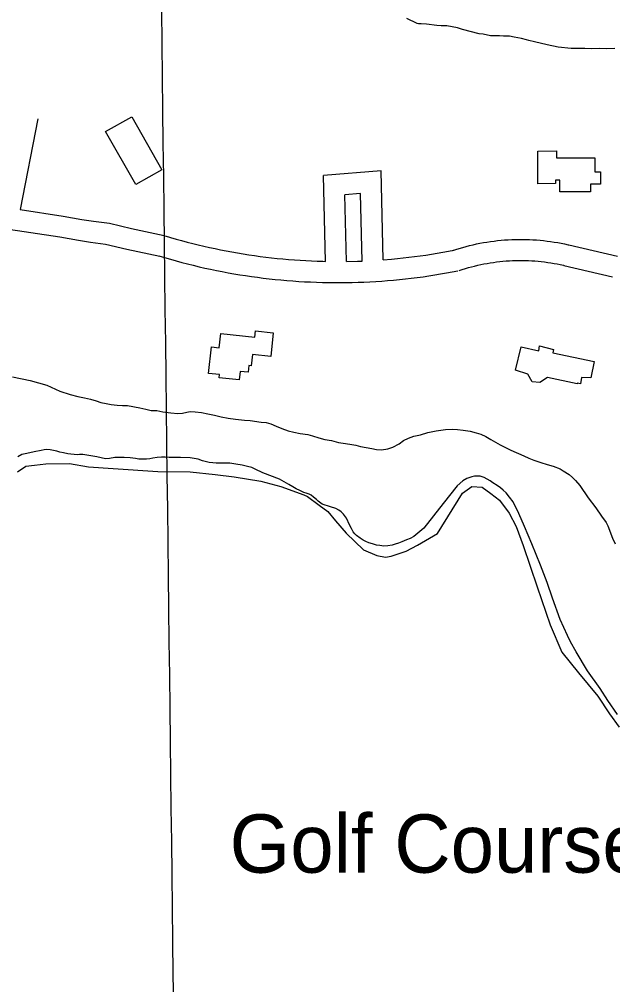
# Model space of a CAD drawing. Extents: x 3704301 to 3742427, y 506229 to 532009.
# Drawn here: x 3718892 to 3719736, y 513417 to 514791 of the extents above; entities that cross this region are included whole.
import ezdxf

# ---------------------------------------------------------------- set-up
doc = ezdxf.new("R2010")
doc.units = 0
for name, color, linetype in [('V-BLDG-IDEN', 7, 'Continuous'), ('V-BLDG-OTLN', 7, 'Continuous'), ('V-GRID-MAJR', 7, 'Continuous'), ('V-ROAD-CNTR', 7, 'Continuous'), ('V-SITE-OTLN', 7, 'Continuous'), ('V-SITE-VEGE', 7, 'Continuous'), ('V-TOPO-SHOR', 7, 'Continuous')]:
    doc.layers.add(name, color=color, linetype=linetype)

msp = doc.modelspace()

# ---------------------------------------------------------------- linework, layer by layer
at = {"layer": 'V-BLDG-OTLN'}
for points in [[(3719051.562, 514652.261), (3719094.589, 514576.799), (3719057.545, 514555.678), (3719014.518, 514631.14)], [(3719629.7660000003, 514557.06200000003), (3719629.682, 514603.57), (3719655.978, 514603.619), (3719655.997, 514593.963), (3719710.793, 514594.063), (3719710.83, 514573.936), (3719718.551, 514573.95), (3719718.5840000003, 514556.478), (3719704.631, 514556.456), (3719704.651, 514545.483), (3719660.861, 514545.401), (3719660.828, 514562.264), (3719654.617, 514562.254), (3719654.6210000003, 514557.10500000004)], [(3719252.873, 514344.902), (3719249.3710000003, 514311.04600000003), (3719223.345, 514313.737), (3719221.698, 514297.83), (3719218.4620000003, 514298.164), (3719217.485, 514288.707), (3719205.9080000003, 514289.905), (3719204.648, 514277.733), (3719176.14, 514280.68200000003), (3719176.617, 514285.297), (3719161.079, 514286.90400000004), (3719164.987, 514324.7), (3719176.191, 514323.543), (3719178.27, 514343.63800000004), (3719226.605, 514338.639), (3719227.531, 514347.523)], [(3719685.341, 514272.21400000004), (3719643.287, 514280.988), (3719632.5840000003, 514274.053), (3719621.748, 514275.229), (3719615.489, 514285.94200000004), (3719597.819, 514291.73600000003), (3719606.063, 514324.993), (3719631.167, 514319.32), (3719631.7320000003, 514326.091), (3719652.095, 514321.016), (3719650.8200000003, 514316.262), (3719709.8370000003, 514303.708), (3719704.807, 514280.64400000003), (3719691.9560000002, 514281.108), (3719690.071, 514272.292), (3719685.554, 514273.232)]]:
    msp.add_lwpolyline(points, close=True, dxfattribs=at)
at = {"layer": 'V-GRID-MAJR'}
msp.add_spline([(3719130.791, 511775.213), (3719057.661, 517832.646), (3718984.494, 523893.163), (3718911.326, 529953.694), (3718911.289, 529956.764)], degree=3, dxfattribs=at)
at = {"layer": 'V-ROAD-CNTR'}
for points in [[(3718917.9881250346, 514649.22467537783), (3718892.7591754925, 514520.16793349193)], [(3719406.4941480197, 514575.5548227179), (3719324.34931231, 514568.9508359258)], [(3719327.3513063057, 514446.467080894), (3719324.34931231, 514568.9508359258)], [(3719409.6041418, 514448.69007644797), (3719406.4941480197, 514575.5548227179)], [(3719377.2812064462, 514543.10888760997), (3719355.037250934, 514541.320891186)], [(3719357.3642462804, 514446.28908124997), (3719355.037250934, 514541.320891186)], [(3719379.636201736, 514446.97207988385), (3719377.2812064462, 514543.10888760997)], [(3718892.758175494, 514520.16793349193), (3718953.9110531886, 514511.00695181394), (3718980.7559994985, 514506.2889612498), (3718997.365966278, 514503.6829664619), (3719019.8249213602, 514500.70997240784), (3719051.2918584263, 514493.30198722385), (3719097.89476522, 514483.1960074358)], [(3718783.6913936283, 514506.1709614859), (3718949.091062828, 514481.3950110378), (3718975.8340093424, 514476.69502043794), (3718993.071974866, 514473.98902584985), (3719014.406932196, 514471.16603149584), (3719044.6758716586, 514464.040045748), (3719091.536777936, 514453.878066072)], [(3719099.0117629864, 514482.90900800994), (3719106.89474722, 514480.5520127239), (3719114.7297315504, 514478.29201724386), (3719122.586715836, 514476.10702161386), (3719130.4637000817, 514473.99802583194), (3719138.360684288, 514471.96602989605), (3719146.2766684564, 514470.00903380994), (3719154.212652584, 514468.13003756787), (3719162.1656366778, 514466.32604117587), (3719170.13462074, 514464.59904462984), (3719178.120604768, 514462.94904793), (3719186.1225887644, 514461.37605107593), (3719194.1395727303, 514459.88105406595), (3719202.1695566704, 514458.46305690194), (3719210.21454058, 514457.1220595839), (3719218.2695244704, 514455.8580621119), (3719226.336508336, 514454.673064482), (3719234.4164921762, 514453.56606669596), (3719242.506475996, 514452.5360687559), (3719250.605459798, 514451.5840706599), (3719258.713443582, 514450.71007240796), (3719266.8294273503, 514449.9140739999), (3719274.951411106, 514449.19707543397), (3719283.080394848, 514448.55907671), (3719291.2173785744, 514447.998077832), (3719299.357362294, 514447.51607879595), (3719307.502346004, 514447.113079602), (3719315.6513297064, 514446.78808025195), (3719323.800313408, 514446.5410807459), (3719327.3513063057, 514446.467080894)], [(3719508.280944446, 514462.007049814), (3719512.9659350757, 514463.5390467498), (3719517.795925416, 514465.031043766), (3719522.64891571, 514466.441040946), (3719527.5259059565, 514467.7720382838), (3719532.4258961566, 514469.0210357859), (3719537.34388632, 514470.1880334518), (3719542.280876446, 514471.2720312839), (3719547.234866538, 514472.27502927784), (3719552.205856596, 514473.19502743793), (3719557.1918466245, 514474.032025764), (3719562.18883663, 514474.786024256), (3719567.200826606, 514475.45602291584), (3719572.2198165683, 514476.0430217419), (3719577.249806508, 514476.5470207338), (3719582.287796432, 514476.96701989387), (3719587.3317863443, 514477.3020192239), (3719592.3797762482, 514477.55401871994), (3719597.431766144, 514477.72201838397), (3719602.487756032, 514477.8050182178), (3719607.540745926, 514477.80401821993), (3719612.594735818, 514477.72001838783), (3719617.64872571, 514477.550018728), (3719622.6967156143, 514477.2970192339), (3719627.739705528, 514476.960019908), (3719632.777695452, 514476.5390207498), (3719637.806685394, 514476.0350217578), (3719642.8276753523, 514475.447022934), (3719647.837665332, 514474.77402427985), (3719652.836655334, 514474.01902579), (3719657.8206453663, 514473.18002746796), (3719662.790635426, 514472.25902931), (3719667.7466255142, 514471.25503131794), (3719672.6286157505, 514470.1810334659), (3719673.556613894, 514469.96703389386)], [(3719409.6041418, 514448.69007644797), (3719421.553117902, 514449.7130744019), (3719429.6691016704, 514450.48707285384), (3719437.780085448, 514451.34007114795), (3719445.881069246, 514452.27106928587), (3719453.97405306, 514453.2800672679), (3719462.0560368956, 514454.36606509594), (3719470.127020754, 514455.53106276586), (3719478.187004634, 514456.773060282), (3719486.2339885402, 514458.093057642), (3719494.267972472, 514459.49005484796), (3719502.2889564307, 514460.96505189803), (3719510.0929408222, 514462.47604887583)], [(3719673.6166137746, 514469.95303392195), (3719742.8794752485, 514453.742066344)], [(3719090.4197801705, 514454.16506549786), (3719098.4407641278, 514451.768070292), (3719106.553747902, 514449.42807497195), (3719114.688731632, 514447.16507949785), (3719122.8457153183, 514444.982083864), (3719131.022698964, 514442.87608807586), (3719139.2206825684, 514440.85109212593), (3719147.4366661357, 514438.90409602), (3719155.671649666, 514437.036099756), (3719163.9246331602, 514435.2491033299), (3719172.192616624, 514433.54110674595), (3719180.478600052, 514431.91211000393), (3719188.7795834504, 514430.363113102), (3719197.0935668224, 514428.89511603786), (3719205.422550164, 514427.5061188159), (3719213.765533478, 514426.19812143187), (3719222.120516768, 514424.9711238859), (3719230.4845000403, 514423.82412617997), (3719238.860483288, 514422.7581283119), (3719247.2474665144, 514421.7721302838), (3719255.6434497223, 514420.868132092), (3719264.0454329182, 514420.04413373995), (3719272.457416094, 514419.30113522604), (3719280.876399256, 514418.63913654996), (3719289.29938241, 514418.060137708), (3719297.72936555, 514417.56013870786), (3719306.1623486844, 514417.14313954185), (3719314.59933181, 514416.8061402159), (3719323.040314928, 514416.55114072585), (3719331.4822980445, 514416.3781410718), (3719339.925281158, 514416.28514125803), (3719348.368264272, 514416.2741412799), (3719356.8122473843, 514416.34414114), (3719365.2552304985, 514416.49614083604), (3719373.6962136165, 514416.7291403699), (3719382.1351967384, 514417.04413974), (3719390.568179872, 514417.440138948), (3719398.9981630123, 514417.91713799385), (3719407.42414616, 514418.475136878), (3719415.8441293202, 514419.11513559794), (3719424.257112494, 514419.8351341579), (3719432.6630956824, 514420.63713255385), (3719441.060078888, 514421.52013078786), (3719449.44906211, 514422.48312886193), (3719457.828045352, 514423.5281267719), (3719466.196028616, 514424.6521245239), (3719474.5550118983, 514425.8591221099), (3719482.8989952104, 514427.14511953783), (3719491.2319785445, 514428.51111680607), (3719499.551961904, 514429.95811391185), (3719507.8549452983, 514431.485110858), (3719515.796929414, 514433.02410778)], [(3719357.3642462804, 514446.28908124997), (3719372.722215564, 514446.7130804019), (3719379.636201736, 514446.97207988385)], [(3719517.60892579, 514433.4931068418), (3719522.057916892, 514434.94910393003), (3719526.409908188, 514436.2931012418), (3719530.784899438, 514437.5650986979), (3719535.179890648, 514438.7640962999), (3719539.5938818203, 514439.8890940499), (3719544.0258729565, 514440.9400919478), (3719548.474864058, 514441.91808999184), (3719552.9408551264, 514442.82108818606), (3719557.4198461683, 514443.65108652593), (3719561.911837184, 514444.40408501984), (3719566.416828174, 514445.0840836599), (3719570.9308191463, 514445.6880824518), (3719575.4578100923, 514446.217081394), (3719579.9898010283, 514446.67108048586), (3719584.5297919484, 514447.0490797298), (3719589.07378286, 514447.35207912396), (3719593.6257737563, 514447.57807867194), (3719598.1777646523, 514447.730078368), (3719602.7317555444, 514447.805078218), (3719607.2887464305, 514447.8040782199), (3719611.8427373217, 514447.728078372), (3719616.394728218, 514447.576078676), (3719620.944719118, 514447.347079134), (3719625.491710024, 514447.04407973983), (3719630.029700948, 514446.665080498), (3719634.5626918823, 514446.20908140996), (3719639.087682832, 514445.67908246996), (3719643.601673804, 514445.07408367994), (3719648.106664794, 514444.393085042), (3719652.5986558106, 514443.6380865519), (3719657.0786468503, 514442.8070882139), (3719661.5426379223, 514441.90309002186), (3719666.044628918, 514440.91109200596), (3719666.840627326, 514440.7290923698)], [(3719666.7806274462, 514440.74309234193), (3719736.04348892, 514424.532124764)]]:
    msp.add_lwpolyline(points, dxfattribs=at)
at = {"layer": 'V-SITE-OTLN'}
for points in [[(3718888.855, 514146.702), (3718900.889, 514155.011), (3718913.034, 514156.563), (3718929.231, 514158.179), (3718963.0270000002, 514158.734), (3718990.151, 514153.768), (3719025.344, 514151.64), (3719088.967, 514147.272), (3719134.951, 514146.674), (3719170.164, 514143.19200000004), (3719197.267, 514139.579), (3719235.227, 514133.439), (3719263.752, 514125.792), (3719296.393, 514114.158), (3719301.842, 514111.542), (3719318.2630000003, 514099.641), (3719330.5840000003, 514090.378), (3719341.6210000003, 514077.038), (3719356.778, 514059.707), (3719381.5100000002, 514035.772), (3719400.568, 514027.972), (3719412.778, 514025.467), (3719420.866, 514026.952), (3719442.384, 514034.064), (3719458.473, 514042.441), (3719486.597, 514059.128), (3719522.166, 514116.5), (3719535.529, 514126.183), (3719550.4220000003, 514125.075), (3719562.7430000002, 514115.81200000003), (3719575.0640000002, 514106.549), (3719588.892, 514087.84500000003), (3719598.663, 514069.075), (3719608.569, 514042.193), (3719628.468, 513983.022), (3719646.926, 513929.237), (3719663.789, 513890.30100000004), (3719687.258, 513860.93700000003), (3719714.844, 513827.585), (3719731.488, 513802.16500000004)], [(3719731.488, 513802.16500000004), (3719745.316, 513783.461)]]:
    msp.add_lwpolyline(points, dxfattribs=at)
at = {"layer": 'V-SITE-VEGE'}
msp.add_lwpolyline([(3719739.1010000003, 514749.369), (3719727.14, 514748.89), (3719717.904, 514749.482), (3719705.401, 514749.005), (3719696.707, 514749.59500000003), (3719677.142, 514749.697), (3719658.6720000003, 514751.425), (3719642.929, 514754.77), (3719625.017, 514759.212), (3719616.872, 514760.887), (3719613.6180000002, 514761.99100000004), (3719606.56, 514763.658), (3719595.702, 514765.891), (3719589.185, 514767.015), (3719580.489, 514767.058), (3719575.058, 514767.629), (3719562.0160000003, 514767.701), (3719551.698, 514769.927), (3719546.267, 514770.501), (3719522.3850000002, 514776.606), (3719515.33, 514778.815), (3719500.128, 514781.613), (3719491.975, 514781.65400000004), (3719486.001, 514782.232), (3719471.335, 514783.94), (3719463.7290000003, 514784.523), (3719459.923, 514784.544), (3719457.753, 514785.099), (3719443.115, 514792.24)], dxfattribs=at)
at = {"layer": 'V-TOPO-SHOR'}
for points in [[(3718881.873, 514282.304), (3718907.289, 514277.101), (3718930.562, 514270.06200000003), (3718949.515, 514261.528), (3718964.203, 514256.973), (3718974.967, 514254.075), (3718984.292, 514252.205), (3718992.938, 514250.472), (3719001.001, 514247.757), (3719007.8540000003, 514245.77), (3719015.45, 514244.17100000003), (3719022.219, 514242.782), (3719031.08, 514241.65400000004), (3719038.429, 514241.473), (3719045.398, 514241.512), (3719063.068, 514237.98000000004), (3719071.791, 514236.173), (3719079.3910000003, 514234.275)], [(3719079.3910000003, 514234.275), (3719087.464, 514233.966), (3719095.807, 514232.452), (3719107.078, 514230.765), (3719117.434, 514229.808), (3719124.094, 514230.443), (3719130.068, 514231.813), (3719135, 514232.72000000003), (3719142.049, 514232.46), (3719150.686, 514231.32800000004), (3719160.008, 514229.60500000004), (3719169.484, 514227.588), (3719178.669, 514225.04000000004), (3719189.041, 514223.261), (3719199.1780000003, 514222.003), (3719212.093, 514220.565), (3719219.974, 514219.945), (3719235.753, 514217.356), (3719242.88, 514216.873), (3719249.4280000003, 514215.255), (3719257.13, 514211.71), (3719265.349, 514208.62200000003), (3719274.321, 514205.396), (3719282.153, 514203.2), (3719291.2460000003, 514201.626), (3719302.0640000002, 514200.079), (3719308.99, 514198.169), (3719317.882, 514195.166), (3719326.461, 514193.059), (3719335.708, 514191.261), (3719346.0160000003, 514188.80700000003), (3719355.7830000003, 514187.39400000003), (3719364.648, 514185.965), (3719370.366, 514184.63300000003), (3719377.063, 514183.01900000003), (3719393.525, 514179.99), (3719399.839, 514178.897), (3719407.194, 514178.266), (3719416.094, 514179.386), (3719423.023, 514181.897), (3719432.011, 514186.767), (3719438.383, 514191.367), (3719445.2970000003, 514194.777), (3719453.122, 514197.53), (3719462.754, 514199.637), (3719473.041, 514203.026), (3719484.845, 514205.318), (3719498.231, 514207.11), (3719507.664, 514207.71400000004), (3719515.24, 514207.315), (3719523.426, 514206.324), (3719533.0470000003, 514204.534), (3719541.774, 514202.57800000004), (3719548.254, 514200.436), (3719555.352, 514197.179), (3719562.69, 514193.026), (3719575.8570000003, 514185.373), (3719591.122, 514177.60500000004), (3719609.612, 514169.81200000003), (3719616.8680000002, 514166.109), (3719623.88, 514163.375), (3719633.901, 514160.242), (3719642.642, 514157.313), (3719651.225, 514154.905), (3719661.477, 514151.251), (3719665.495, 514148.39400000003), (3719674.2060000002, 514142.916), (3719678.994, 514138.797), (3719683.186, 514134.51900000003), (3719689.144, 514127.646), (3719701.35, 514110.00800000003), (3719712.153, 514095.494), (3719720.292, 514083.712), (3719727.034, 514074.754), (3719729.055, 514070.216), (3719735.941, 514052.49), (3719739.668, 514044.607)], [(3719349.757, 514090.081), (3719346.497, 514092.352), (3719342.262, 514094.757), (3719334.653, 514097.104), (3719322.822, 514101.034), (3719316.907, 514105.208), (3719314.474, 514107.342), (3719310.446, 514110.799), (3719307.1040000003, 514113.517), (3719304.157, 514115.042), (3719299.862, 514116.396), (3719296.399, 514117.387), (3719290.7320000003, 514120.14400000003), (3719285.518, 514122.755), (3719280.752, 514125.45), (3719275.149, 514128.956), (3719261.99, 514136.237), (3719238.227, 514145.666), (3719227.275, 514150.882), (3719222.521, 514152.82800000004), (3719216.273, 514154.599), (3719208.974, 514156.352), (3719199.9560000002, 514157.78), (3719191.467, 514158.99), (3719184.1950000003, 514159.244), (3719177.377, 514159.06), (3719171.68, 514159.115), (3719166.951, 514159.637), (3719161.6920000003, 514160.37700000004), (3719157.933, 514161.065), (3719152.285, 514162.695), (3719146.401, 514165.07300000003), (3719134.904, 514166.984), (3719121.108, 514167.281), (3719111.444, 514167.123), (3719104.917, 514167.467), (3719099.365, 514167.89900000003), (3719093.8170000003, 514167.958), (3719087.6070000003, 514167.33400000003), (3719081.7770000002, 514166.412), (3719077.521, 514165.444), (3719072.659, 514164.83900000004), (3719066.8140000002, 514164.743), (3719061.563, 514165.108), (3719056.83, 514165.77900000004), (3719049.467, 514166.859), (3719040.839, 514167.391), (3719027.503, 514167.174), (3719019.952, 514166.076), (3719014.113, 514165.60500000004), (3719001.784, 514168.026), (3718990.579, 514170.242), (3718982.0100000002, 514171.749), (3718977.066, 514171.596), (3718973.855, 514170.94200000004), (3718960.494, 514172.298), (3718954.323, 514173.771), (3718949.056, 514175.032), (3718945.066, 514176.091), (3718940.399, 514177.365), (3718935.738, 514178.262), (3718931.011, 514178.561), (3718927.044, 514178.196), (3718922.864, 514177.228), (3718912.9250000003, 514175.41500000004), (3718902.323, 514173.068), (3718895.304, 514171.456), (3718889.3570000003, 514168.436)], [(3719742.9960000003, 513801.604), (3719729.11, 513821.16500000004), (3719718.336, 513838.45), (3719700.234, 513863.78500000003), (3719684.128, 513890.727), (3719676.1040000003, 513904.76), (3719671.988, 513913.68700000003), (3719661.27, 513936.518), (3719650.506, 513966.92100000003), (3719643.097, 513989.13300000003), (3719633.469, 514014.234), (3719621.2120000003, 514044.161), (3719610.384, 514069.24100000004), (3719602.515, 514087.548), (3719594.452, 514103.979), (3719589.47, 514110.717), (3719584.497, 514116.931), (3719580.46, 514120.836), (3719576.436, 514124.07), (3719571.582, 514127.586), (3719565.674, 514131.387), (3719561.957, 514134.175), (3719553.111, 514138.826), (3719547.3850000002, 514140.60500000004), (3719543.187, 514140.76300000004), (3719539.369, 514140.474), (3719535.556, 514139.889), (3719532.572, 514139.014), (3719528.478, 514137.374), (3719522.9080000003, 514134.28500000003), (3719514.558, 514127.02900000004), (3719494.737, 514101.673), (3719467.507, 514066.451), (3719453.159, 514054.901), (3719447.961, 514051.968), (3719442.669, 514050.082), (3719435.968, 514047.423), (3719431.503, 514045.402), (3719426.5100000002, 514043.672), (3719422.1070000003, 514042.55100000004), (3719415.906, 514041.474), (3719410.288, 514041.159), (3719404.808, 514041.818), (3719399.921, 514042.637), (3719394.125, 514044.19200000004), (3719389.079, 514045.832), (3719384.629, 514047.559), (3719380.924, 514049.521), (3719376.525, 514052.672), (3719371.593, 514056.338), (3719369.004, 514058.84500000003), (3719366.936, 514061.659), (3719364.315, 514066.11100000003), (3719361.451, 514071.537), (3719357.1040000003, 514080.759), (3719352.887, 514086.61), (3719349.757, 514090.081)]]:
    msp.add_lwpolyline(points, dxfattribs=at)

# ---------------------------------------------------------------- texts
at = {"layer": 'V-BLDG-IDEN'}
msp.add_text('Golf Course', height=82.99983200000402, dxfattribs=at).set_placement((3719190.9385791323, 513576.18782145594))

doc.saveas('drawing.dxf')
